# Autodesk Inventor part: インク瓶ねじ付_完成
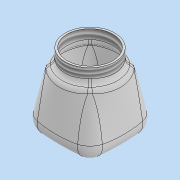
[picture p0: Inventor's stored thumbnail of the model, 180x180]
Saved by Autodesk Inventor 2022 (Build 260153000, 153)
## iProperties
Created: 2021-07
Part Number: インク瓶ねじ付_完成
Material: 一般
Document SubType Name: Modeling
Designer: DesignLab
Density: 1 g/cm^3
Appearance: 既定
Author: DesignLab
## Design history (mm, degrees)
sketch "スケッチ1"
  geometry: L1 (-17.5, -17.5)-(17.5, -17.5); L2 (17.5, -17.5)-(17.5, 17.5); L3 (17.5, 17.5)-(-17.5, 17.5); L4 (-17.5, 17.5)-(-17.5, -17.5); L5 (-17.5, -17.5)-(17.5, 17.5); L6 (17.5, -17.5)-(-17.5, 17.5); 1 further point
  constraints: 12 end point, 2 midpoint, 2 parallel, 1 horizontal, 1 perpendicular
  dimensions: "d0" = 35 distance of L3.end L2.end; "d1" = 35 distance of L2.end L1.end
node "作業平面1"
sketch "スケッチ2"
  geometry: C1 r 15 at (0, 0); 1 further point
  constraints: 1 centre point, 1 coincident
  dimensions: "d3" = 30 diameter of C1
feature "ロフト1" sketch "スケッチ2" dims "d4" = 0, "d5" = 90 deg, "d6" = 0, "d7" = 90 deg
sketch "スケッチ3"
  geometry: C1 r 12.5 at (0, 0); 1 further point
  constraints: 1 centre point, 1 coincident
  dimensions: "d8" = 25 diameter of C1
extrude "押し出し1" join sketch "スケッチ3" distance "d9" = 7; taper "d10" = 0 deg
fillet "フィレット1" dims "d11" = 7
fillet "フィレット2" dims "d12" = 3
feature "シェル1" dims "d13" = 1
feature "ねじ1" dims "d14" = 4.963, "d15" = 0
feature "ねじ2" dims "d16" = 4.963, "d17" = 0
node "ソリッド1"
